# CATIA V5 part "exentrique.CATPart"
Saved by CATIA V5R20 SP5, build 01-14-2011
Part number: exentrique
Bounding box of the stored display mesh (mm): x -15 to 5, y -25 to 25, z -24.951 to 24.951
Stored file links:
  U:\2A\IAO\ThinkMotion\exentrique.CATPart
  U:\2A\IAO\ThinkMotion\MECANISME 1517.CATProduct
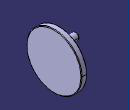
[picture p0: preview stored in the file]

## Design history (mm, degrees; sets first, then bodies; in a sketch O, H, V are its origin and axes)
External parameters (linked from other documents)
  External.R_exentrique = 10 mm
Set1
  Plane1 "Plan_ref": linked copy from another document
  Point1: linked copy from another document
Body1 (main body)
  Sketch1 on Plane1, origin (0, 0, 0), H (0, 1, 0), V (0, 0, 1)
    circle A1 centre (0, 0) radius 25
    point P1 (0, 0)
    radius A1 = 25 {= 25mm}
    coincidence: P1 V, P1 H
  Pad1: profile Sketch1, direction (1, 0, 0), length 5
  Sketch2 on Plane1, origin (0, 0, 0), H (0, 1, 0), V (0, 0, 1)
    circle A1 centre (0, 10) radius 3
    point P1 (0, 10)
    reference projected point E1 (0, 10) from Point1
    radius A1 = 3
    coincidence: P1 V, P1 E1
  Pad2: profile Sketch2, direction (-1, 0, 0), length 15
  Fillet1: radius 0.5, on face of Pad2 from Sketch2.A1; face of Pad1 from Sketch1.A1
